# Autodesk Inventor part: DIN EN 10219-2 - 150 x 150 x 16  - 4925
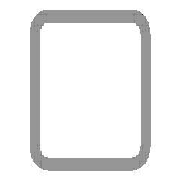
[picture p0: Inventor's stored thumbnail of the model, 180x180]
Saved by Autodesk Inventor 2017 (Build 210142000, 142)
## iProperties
IsCustomPart: 1
Created: 2017-11
Part Number: DIN EN 10219-2 - 150 x 150 x 16  - 4925
Material: Steel, Mild
Description: Cold formed welded structural hollow sections of non-alloy and fine grain structural steel
Document SubType Name: Modeling
Standard: DIN
Designer: iusti
Standard Revision: 2006-07
Standards Organization: DIN
Language: en-US
Size Designation: 150 x 150 x 16
Categories: <MemberInstance><Categories><Category DisplayName="Structural Shapes" InternalName="089c4875-fa83-4c05-b084-43b9cc11f5ed" Mnemonic="GRDR"><CategoryParameter Dis
Stock Number: 150 x 150 x 16
Density: 7.85 g/cm^3
Appearance: Semi-Polished
Mass: 289079 g
Surface Area: 46181.3 cm^2
Volume: 36825.4 cm^3
_CCFamilyMember: 76
_CCFamilyDisplayName: DIN EN 10219-2 (Square Hollow Section - Cold Formed) - Cold formed welded structural hollow sections of non-alloy and fine grain structural steel
_FrameMemberDoc: Frame Member File
_Version: 15.0.0
_GetPNFromCC: 1
G_L: 4925.000 mm
G_W: 150.000 mm
G_H: 150.000 mm
+9097C832-944A-4210-ACA6-A5D58FB62A7C+CUTDETAIL1: Cut
Author: iusti
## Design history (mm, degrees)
node "Start plane"
node "End plane"
sketch "Sketch"
  geometry: L1 (-75, -27)-(-75, 27); L2 (-27, 75)-(27, 75); L3 (75, 27)-(75, -27); L4 (27, -75)-(-27, -75); L5 (-27, 59)-(27, 59); L6 (59, 27)-(59, -27); L7 (27, -59)-(-27, -59); L8 (-59, -27)-(-59, 27); L9 (0, 118.918)-(0, -118.918) reference; L10 (-118.918, 0)-(118.918, 0) reference; A1 r 48 centre (-27, -27) between (-75, -27) and (-27, -75); A2 r 48 centre (-27, 27) between (-27, 75) and (-75, 27); A3 r 48 centre (27, 27) between (75, 27) and (27, 75); A4 r 48 centre (27, -27) between (27, -75) and (75, -27); A5 r 32 centre (-27, 27) between (-27, 59) and (-59, 27); A6 r 32 centre (27, 27) between (59, 27) and (27, 59); A7 r 32 centre (27, -27) between (27, -59) and (59, -27); A8 r 32 centre (-27, -27) between (-59, -27) and (-27, -59)
  constraints: 16 end point, 16 point on circle, 8 centre point, 8 tangent, 4 parallel, 3 equal radius, 2 perpendicular, 7 other
  dimensions: "d7" = 48 radius of A1 (= G_IR); "d10" = 150 distance between parallel lines of L2 L4 (= G_H); "d11" = 150 distance between parallel lines of L1 L3 (= G_W); "d12" = 16 distance between parallel lines of L3 L6 (= G_T); "d15" = 75 distance between parallel lines of L2 L10 (= 0.5 x d10); "d16" = 75 distance between parallel lines of L9 L3 (= 0.5 x d11)
extrude "Body" new body sketch "Sketch" stored distance "d3" = 4925 (= G_L); taper "d4" = 0 deg
node "Driven Length"
  sketch "Sketch3"
    geometry: L1 (0, 0)-(10, 0) reference
    constraints: 2 end point, 1 horizontal
  workplane "Work Plane3"
  sketch "Sketch4"
    geometry: L1 (-2, 75)-(12, 75) reference; L2 (-2, 5000)-(12, 5000) reference
    dimensions: "d18" = 4925 distance between parallel lines of L1 L2 (derived)
workplane "Work Plane4"
split "Split1"
body "Solid1"
other parameters: "G_W" = 150 [user parameter; used in 1 equation term], "G_H" = 150 [user parameter; used in 1 equation term], "G_T" = 16 [user parameter; used in 1 equation term], "G_IR" = 48 [user parameter; used in 1 equation term], "G_L" = 4925 (= d18) [user parameter; used in 1 equation term], "G_OFFSET_START" = -75 [user parameter; used in 1 equation term], "G_OFFSET_END" = 0 [user parameter; used in 1 equation term], "d13" = 75 (= -G_OFFSET_START), "d17" = 90 deg
